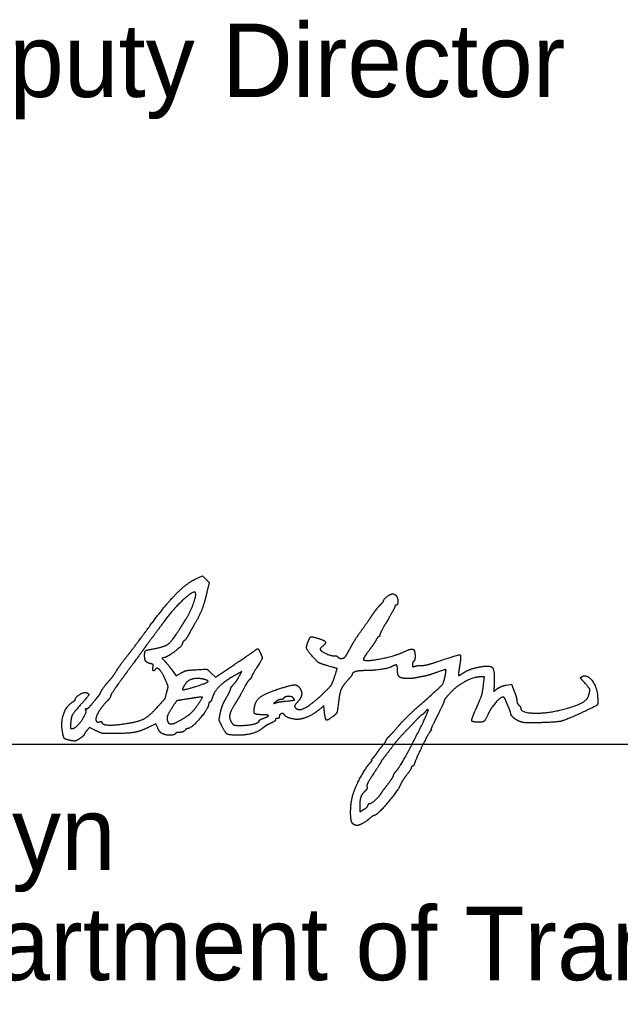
# Model space of a CAD drawing. Extents: x 0 to 34, y -3.9 to 26.2.
# Drawn here: x 25.914 to 27.06, y 4.977 to 6.851 of the extents above; entities that cross this region are included whole.
import ezdxf

# ---------------------------------------------------------------- set-up
doc = ezdxf.new("R2010")
doc.units = 0
doc.layers.add('SH_Data', color=7, linetype='Continuous')
doc.layers.add('SH_Text', color=7, linetype='Continuous')

msp = doc.modelspace()

# ---------------------------------------------------------------- linework, layer by layer
at = {"layer": 'SH_Data'}
msp.add_line((24.7652, 5.4694), (28.2652, 5.4694), dxfattribs=at)
at = {"layer": 'SH_Text'}
for points in [[(26.2505, 5.7846), (26.2631, 5.7904), (26.2694, 5.784), (26.2758, 5.7777), (26.2714, 5.759)], [(26.1905, 5.6346), (26.1855, 5.633), (26.1907, 5.6279)], [(26.2795, 5.6049), (26.2876, 5.5973), (26.3239, 5.6214)], [(26.2043, 5.6112), (26.2129, 5.5997), (26.2217, 5.6049)], [(26.3334, 5.5996), (26.3378, 5.6076), (26.3323, 5.6046)], [(26.7992, 5.5837), (26.8007, 5.5975), (26.7929, 5.5975)], [(26.8431, 5.5821), (26.8527, 5.5836), (26.8578, 5.5701)], [(26.4951, 5.5359), (26.4945, 5.5428), (26.4886, 5.5376)], [(26.1775, 5.5003), (26.1742, 5.5084), (26.1603, 5.5015)], [(26.0589, 5.4953), (26.0474, 5.5011), (26.0423, 5.4953)], [(26.5629, 5.3498), (26.5629, 5.3404), (26.5704, 5.3448)]]:
    msp.add_lwpolyline(points, dxfattribs=at)
for points in [[(26.1609, 5.6927), (26.1906, 5.7333), (26.2324, 5.7762), (26.2505, 5.7846)], [(26.249, 5.7587), (26.2454, 5.7624), (26.2068, 5.7267), (26.1914, 5.7054)], [(26.2307, 5.7067), (26.2401, 5.7216), (26.2521, 5.7556), (26.249, 5.7587)], [(26.2714, 5.759), (26.2664, 5.7378), (26.2572, 5.7142), (26.2478, 5.6983)], [(26.6085, 5.7426), (26.6085, 5.7455), (26.6217, 5.7558), (26.6254, 5.7558)], [(26.6254, 5.7558), (26.6275, 5.7559), (26.6304, 5.7546), (26.632, 5.753)], [(26.632, 5.753), (26.6355, 5.7495), (26.6359, 5.7343), (26.6325, 5.7343)], [(26.5881, 5.7173), (26.5921, 5.7231), (26.5983, 5.7309), (26.6019, 5.7345)], [(26.6019, 5.7345), (26.6055, 5.7382), (26.6085, 5.7418), (26.6085, 5.7426)], [(26.6325, 5.7343), (26.6312, 5.7343), (26.6301, 5.7332), (26.6301, 5.7318)], [(26.5665, 5.6863), (26.5744, 5.6975), (26.5842, 5.7115), (26.5881, 5.7173)], [(26.6301, 5.7318), (26.6301, 5.7304), (26.6236, 5.7183), (26.6157, 5.7049)], [(26.1914, 5.7054), (26.1878, 5.7004), (26.1784, 5.6878), (26.1705, 5.6773)], [(26.2202, 5.69), (26.2234, 5.6952), (26.2282, 5.7027), (26.2307, 5.7067)], [(26.2478, 5.6983), (26.2443, 5.6924), (26.2391, 5.6832), (26.2362, 5.6779)], [(26.6157, 5.7049), (26.6078, 5.6915), (26.6013, 5.6792), (26.6013, 5.6774)], [(26.1207, 5.6392), (26.1296, 5.6506), (26.1477, 5.6746), (26.1609, 5.6927)], [(26.1705, 5.6773), (26.1626, 5.6668), (26.1545, 5.6558), (26.1525, 5.6528)], [(26.1704, 5.6514), (26.191, 5.6551), (26.205, 5.666), (26.2202, 5.69)], [(26.2362, 5.6779), (26.2334, 5.6726), (26.2296, 5.6674), (26.2278, 5.6664)], [(26.5451, 5.6527), (26.5489, 5.66), (26.5585, 5.6751), (26.5665, 5.6863)], [(26.6013, 5.6774), (26.6013, 5.6757), (26.6004, 5.6743), (26.5993, 5.6743)], [(26.2245, 5.661), (26.2245, 5.6572), (26.1987, 5.6372), (26.1905, 5.6346)], [(26.2278, 5.6664), (26.226, 5.6653), (26.2245, 5.6629), (26.2245, 5.661)], [(26.4742, 5.6351), (26.4627, 5.6482), (26.4605, 5.655), (26.4644, 5.6646)], [(26.4644, 5.6646), (26.4682, 5.6736), (26.4713, 5.6746), (26.484, 5.6709)], [(26.484, 5.6709), (26.496, 5.6673), (26.4989, 5.6611), (26.4912, 5.6553)], [(26.594, 5.6677), (26.5922, 5.6641), (26.5861, 5.655), (26.5804, 5.6475)], [(26.5993, 5.6743), (26.5982, 5.6743), (26.5958, 5.6713), (26.594, 5.6677)], [(26.0992, 5.6099), (26.1021, 5.6147), (26.1118, 5.6279), (26.1207, 5.6392)], [(26.1525, 5.6528), (26.1505, 5.6499), (26.1351, 5.6289), (26.1184, 5.6063)], [(26.1525, 5.6393), (26.1525, 5.6461), (26.1566, 5.6489), (26.1704, 5.6514)], [(26.1635, 5.6229), (26.1563, 5.6247), (26.1525, 5.6304), (26.1525, 5.6393)], [(26.3239, 5.6214), (26.3438, 5.6346), (26.3614, 5.6466), (26.363, 5.6479)], [(26.363, 5.6479), (26.3675, 5.6517), (26.3699, 5.6508), (26.3729, 5.6442)], [(26.3729, 5.6442), (26.3773, 5.6346), (26.3763, 5.6305), (26.3661, 5.6146)], [(26.4912, 5.6553), (26.4885, 5.6532), (26.487, 5.6504), (26.4879, 5.649)], [(26.4879, 5.649), (26.4906, 5.6453), (26.5105, 5.6371), (26.5152, 5.6378)], [(26.5358, 5.6365), (26.5371, 5.6382), (26.5413, 5.6454), (26.5451, 5.6527)], [(26.5804, 5.6475), (26.5747, 5.64), (26.5701, 5.6328), (26.5701, 5.6314)], [(26.5701, 5.6314), (26.5701, 5.6262), (26.6297, 5.6371), (26.6477, 5.6457)], [(26.6477, 5.6457), (26.6606, 5.6519), (26.6685, 5.6487), (26.6685, 5.6373)], [(26.7108, 5.6266), (26.7512, 5.6405), (26.7571, 5.6388), (26.753, 5.615)], [(26.1686, 5.6166), (26.1695, 5.6201), (26.1683, 5.6217), (26.1635, 5.6229)], [(26.1907, 5.6279), (26.1935, 5.625), (26.1997, 5.6175), (26.2043, 5.6112)], [(26.4977, 5.62), (26.4869, 5.6231), (26.482, 5.6263), (26.4742, 5.6351)], [(26.5152, 5.6378), (26.5174, 5.6382), (26.52, 5.6374), (26.5208, 5.636)], [(26.5208, 5.636), (26.523, 5.6325), (26.533, 5.6329), (26.5358, 5.6365)], [(26.6661, 5.6275), (26.6648, 5.6267), (26.6637, 5.6239), (26.6637, 5.6212)], [(26.6637, 5.6212), (26.6637, 5.6173), (26.6647, 5.6167), (26.6691, 5.6181)], [(26.6685, 5.6373), (26.6685, 5.6327), (26.6674, 5.6283), (26.6661, 5.6275)], [(26.682, 5.6195), (26.6862, 5.6194), (26.6991, 5.6226), (26.7108, 5.6266)], [(26.0829, 5.588), (26.0895, 5.5953), (26.0937, 5.601), (26.0992, 5.6099)], [(26.1184, 5.6063), (26.1016, 5.5836), (26.0878, 5.5635), (26.0877, 5.5615)], [(26.1728, 5.6118), (26.1704, 5.6079), (26.1672, 5.6115), (26.1686, 5.6166)], [(26.1916, 5.5932), (26.1855, 5.6069), (26.1758, 5.6166), (26.1728, 5.6118)], [(26.2217, 5.6049), (26.2282, 5.6088), (26.2358, 5.6104), (26.2509, 5.6113)], [(26.2509, 5.6113), (26.2712, 5.6125), (26.2714, 5.6125), (26.2795, 5.6049)], [(26.3323, 5.6046), (26.3089, 5.5921), (26.2861, 5.5714), (26.282, 5.5589)], [(26.3661, 5.6146), (26.3608, 5.6064), (26.3565, 5.5988), (26.3565, 5.5977)], [(26.5145, 5.5962), (26.5201, 5.6131), (26.5198, 5.6136), (26.4977, 5.62)], [(26.5485, 5.6023), (26.5485, 5.6014), (26.5443, 5.596), (26.5391, 5.5903)], [(26.5727, 5.6095), (26.5612, 5.6095), (26.5485, 5.6057), (26.5485, 5.6023)], [(26.6235, 5.6169), (26.6179, 5.6139), (26.5877, 5.6095), (26.5727, 5.6095)], [(26.6349, 5.6122), (26.6349, 5.6195), (26.6312, 5.621), (26.6235, 5.6169)], [(26.6542, 5.5945), (26.6418, 5.5946), (26.6349, 5.6009), (26.6349, 5.6122)], [(26.6691, 5.6181), (26.6721, 5.619), (26.6779, 5.6197), (26.682, 5.6195)], [(26.7055, 5.6046), (26.6977, 5.6019), (26.688, 5.5992), (26.6841, 5.5985)], [(26.7261, 5.6), (26.7282, 5.6115), (26.7265, 5.6119), (26.7055, 5.6046)], [(26.753, 5.615), (26.7516, 5.6073), (26.7509, 5.6007), (26.7514, 5.6002)], [(26.7514, 5.6002), (26.7518, 5.5998), (26.7552, 5.6015), (26.7589, 5.6041)], [(26.7589, 5.6041), (26.7662, 5.6092), (26.7844, 5.6155), (26.7981, 5.6176)], [(26.7981, 5.6176), (26.8127, 5.6199), (26.8204, 5.6095), (26.8196, 5.5883)], [(26.0685, 5.5675), (26.0685, 5.5691), (26.0776, 5.5821), (26.0829, 5.588)], [(26.1949, 5.5687), (26.1975, 5.5785), (26.1972, 5.5807), (26.1916, 5.5932)], [(26.2301, 5.5841), (26.2231, 5.5734), (26.2276, 5.5725), (26.2521, 5.58)], [(26.2627, 5.5936), (26.2518, 5.5958), (26.2344, 5.5907), (26.2301, 5.5841)], [(26.2521, 5.58), (26.2713, 5.586), (26.2753, 5.5911), (26.2627, 5.5936)], [(26.3206, 5.5815), (26.326, 5.5875), (26.3285, 5.591), (26.3334, 5.5996)], [(26.346, 5.5835), (26.3379, 5.568), (26.3301, 5.5543), (26.324, 5.5446)], [(26.3529, 5.5927), (26.351, 5.5911), (26.3479, 5.5869), (26.346, 5.5835)], [(26.3565, 5.5977), (26.3565, 5.5966), (26.3549, 5.5944), (26.3529, 5.5927)], [(26.4962, 5.5689), (26.5066, 5.579), (26.5107, 5.5851), (26.5145, 5.5962)], [(26.5391, 5.5903), (26.5306, 5.5808), (26.5249, 5.5682), (26.5233, 5.5555)], [(26.6709, 5.5959), (26.6676, 5.5952), (26.6601, 5.5945), (26.6542, 5.5945)], [(26.6841, 5.5985), (26.6801, 5.5979), (26.6742, 5.5967), (26.6709, 5.5959)], [(26.6813, 5.547), (26.7168, 5.5785), (26.7237, 5.5867), (26.7261, 5.6)], [(26.7929, 5.5975), (26.7802, 5.5975), (26.7464, 5.5791), (26.7342, 5.5655)], [(26.7845, 5.5359), (26.7936, 5.5558), (26.7976, 5.5689), (26.7992, 5.5837)], [(26.8196, 5.5883), (26.8189, 5.5699), (26.8188, 5.5701), (26.8265, 5.5757)], [(26.9897, 5.5889), (26.9844, 5.5946), (26.9841, 5.5972), (26.9888, 5.599)], [(26.9888, 5.599), (26.9974, 5.6023), (27.0158, 5.5773), (27.0168, 5.5611)], [(26.9988, 5.5598), (27.0028, 5.5716), (27.0012, 5.5765), (26.9897, 5.5889)], [(26.0205, 5.5555), (26.0206, 5.5592), (26.0373, 5.5692), (26.0411, 5.5677)], [(26.0411, 5.5677), (26.0471, 5.5655), (26.0448, 5.5606), (26.0305, 5.5447)], [(26.0661, 5.5632), (26.0674, 5.5648), (26.0685, 5.5667), (26.0685, 5.5675)], [(26.1753, 5.5382), (26.1914, 5.5558), (26.1917, 5.5563), (26.1949, 5.5687)], [(26.3081, 5.5574), (26.3125, 5.565), (26.3163, 5.5727), (26.3166, 5.5745)], [(26.3166, 5.5745), (26.3169, 5.5762), (26.3186, 5.5794), (26.3206, 5.5815)], [(26.3623, 5.5407), (26.3644, 5.552), (26.3806, 5.5653), (26.3999, 5.5718)], [(26.3999, 5.5718), (26.4317, 5.5824), (26.4451, 5.5828), (26.4502, 5.5733)], [(26.4392, 5.5401), (26.4445, 5.5314), (26.4712, 5.5449), (26.4962, 5.5689)], [(26.4502, 5.5733), (26.4534, 5.5673), (26.45, 5.5559), (26.4426, 5.548)], [(26.7342, 5.5655), (26.7284, 5.5591), (26.7237, 5.5525), (26.7237, 5.5509)], [(26.8265, 5.5757), (26.8303, 5.5783), (26.8377, 5.5812), (26.8431, 5.5821)], [(26.8578, 5.5701), (26.8606, 5.5626), (26.8629, 5.5545), (26.8629, 5.552)], [(25.9956, 5.4939), (25.9927, 5.5124), (26.0034, 5.5424), (26.0158, 5.5501)], [(26.0158, 5.5501), (26.0184, 5.5517), (26.0205, 5.5541), (26.0205, 5.5555)], [(26.0417, 5.537), (26.0431, 5.5366), (26.0486, 5.5417), (26.054, 5.5483)], [(26.054, 5.5483), (26.0593, 5.5549), (26.0648, 5.5616), (26.0661, 5.5632)], [(26.0803, 5.5508), (26.0705, 5.5411), (26.0581, 5.519), (26.0599, 5.5143)], [(26.0877, 5.5615), (26.0876, 5.5595), (26.0843, 5.5547), (26.0803, 5.5508)], [(26.2329, 5.5553), (26.2151, 5.5527), (26.2131, 5.5515), (26.2058, 5.5403)], [(26.2254, 5.5176), (26.2366, 5.5245), (26.2476, 5.5351), (26.2553, 5.5463)], [(26.2503, 5.5579), (26.2447, 5.557), (26.2368, 5.5558), (26.2329, 5.5553)], [(26.2748, 5.5465), (26.2747, 5.538), (26.2416, 5.4991), (26.2345, 5.4991)], [(26.2553, 5.5463), (26.2631, 5.5576), (26.2622, 5.5598), (26.2503, 5.5579)], [(26.2769, 5.5495), (26.2758, 5.5495), (26.2749, 5.5482), (26.2748, 5.5465)], [(26.282, 5.5589), (26.2803, 5.5537), (26.278, 5.5495), (26.2769, 5.5495)], [(26.2972, 5.5295), (26.2988, 5.5372), (26.3037, 5.5498), (26.3081, 5.5574)], [(26.4031, 5.5505), (26.3986, 5.5468), (26.3986, 5.5467), (26.4033, 5.5484)], [(26.412, 5.5543), (26.4097, 5.5543), (26.4057, 5.5526), (26.4031, 5.5505)], [(26.4033, 5.5484), (26.4059, 5.5493), (26.4135, 5.5506), (26.4201, 5.5512)], [(26.4175, 5.5564), (26.4168, 5.5553), (26.4143, 5.5543), (26.412, 5.5543)], [(26.436, 5.5575), (26.4332, 5.5609), (26.4198, 5.5601), (26.4175, 5.5564)], [(26.4201, 5.5512), (26.4368, 5.5527), (26.4392, 5.5537), (26.436, 5.5575)], [(26.4426, 5.548), (26.4398, 5.5451), (26.4383, 5.5415), (26.4392, 5.5401)], [(26.5233, 5.5555), (26.5205, 5.533), (26.5187, 5.5275), (26.5131, 5.5231)], [(26.6372, 5.5042), (26.6444, 5.5126), (26.6642, 5.5319), (26.6813, 5.547)], [(26.7237, 5.5509), (26.7237, 5.5494), (26.7177, 5.5365), (26.7105, 5.5224)], [(26.8361, 5.5591), (26.8318, 5.5591), (26.8135, 5.5386), (26.8088, 5.5284)], [(26.8417, 5.5525), (26.8402, 5.5561), (26.8377, 5.5591), (26.8361, 5.5591)], [(26.8476, 5.5383), (26.8458, 5.5425), (26.8432, 5.5489), (26.8417, 5.5525)], [(26.8629, 5.552), (26.8629, 5.5495), (26.8645, 5.5458), (26.8665, 5.5438)], [(26.9499, 5.5355), (26.9736, 5.5417), (26.9966, 5.5531), (26.9988, 5.5598)], [(27.0168, 5.5611), (27.0177, 5.5458), (27.0151, 5.5426), (26.9917, 5.5317)], [(26.0305, 5.5447), (26.0168, 5.5295), (26.0118, 5.5194), (26.0112, 5.5055)], [(26.016, 5.4995), (26.0224, 5.5005), (26.0425, 5.5289), (26.0405, 5.5341)], [(26.0405, 5.5341), (26.0397, 5.5361), (26.0403, 5.5374), (26.0417, 5.537)], [(26.1188, 5.5089), (26.1415, 5.5125), (26.1611, 5.5227), (26.1753, 5.5382)], [(26.2058, 5.5403), (26.1976, 5.5277), (26.1944, 5.5179), (26.1967, 5.512)], [(26.2992, 5.5055), (26.2948, 5.5146), (26.2946, 5.5169), (26.2972, 5.5295)], [(26.324, 5.5446), (26.316, 5.5319), (26.3138, 5.5167), (26.3189, 5.5099)], [(26.3758, 5.5255), (26.3643, 5.5255), (26.3603, 5.5301), (26.3623, 5.5407)], [(26.4188, 5.5257), (26.4168, 5.5289), (26.4093, 5.5258), (26.4093, 5.5216)], [(26.4886, 5.5376), (26.4792, 5.5295), (26.4592, 5.5188), (26.4501, 5.5172)], [(26.5131, 5.5231), (26.5014, 5.5138), (26.497, 5.517), (26.4951, 5.5359)], [(26.6346, 5.4204), (26.6422, 5.4291), (26.6955, 5.5329), (26.6934, 5.535)], [(26.6877, 5.5309), (26.6853, 5.5279), (26.6827, 5.5255), (26.6819, 5.5255)], [(26.6934, 5.535), (26.6927, 5.5357), (26.6901, 5.5339), (26.6877, 5.5309)], [(26.7919, 5.5111), (26.7774, 5.5111), (26.7758, 5.5165), (26.7845, 5.5359)], [(26.8088, 5.5284), (26.8031, 5.516), (26.7983, 5.5111), (26.7919, 5.5111)], [(26.851, 5.5287), (26.8509, 5.5299), (26.8494, 5.5342), (26.8476, 5.5383)], [(26.8666, 5.5132), (26.8596, 5.5165), (26.8511, 5.5249), (26.851, 5.5287)], [(26.8665, 5.5438), (26.8685, 5.5419), (26.8701, 5.5392), (26.8701, 5.5379)], [(26.8701, 5.5379), (26.8701, 5.5293), (26.9207, 5.5278), (26.9499, 5.5355)], [(26.9917, 5.5317), (26.9569, 5.5153), (26.9359, 5.5106), (26.8965, 5.5101)], [(26.0599, 5.5143), (26.0608, 5.512), (26.0631, 5.511), (26.0661, 5.5118)], [(26.0661, 5.5118), (26.0687, 5.5125), (26.0709, 5.5122), (26.0709, 5.511)], [(26.0709, 5.511), (26.0709, 5.5064), (26.0965, 5.5052), (26.1188, 5.5089)], [(26.1967, 5.512), (26.1987, 5.5068), (26.2122, 5.5094), (26.2254, 5.5176)], [(26.3189, 5.5099), (26.3217, 5.5061), (26.3253, 5.5051), (26.3365, 5.5051)], [(26.3365, 5.5051), (26.3505, 5.5051), (26.3709, 5.5102), (26.3709, 5.5137)], [(26.3709, 5.5137), (26.3709, 5.5148), (26.3746, 5.5169), (26.3792, 5.5186)], [(26.3792, 5.5186), (26.3895, 5.5223), (26.3879, 5.5255), (26.3758, 5.5255)], [(26.3967, 5.5109), (26.3893, 5.5076), (26.3817, 5.5031), (26.3775, 5.4996)], [(26.4021, 5.5158), (26.4021, 5.5145), (26.3997, 5.5123), (26.3967, 5.5109)], [(26.4057, 5.5183), (26.4037, 5.5183), (26.4021, 5.5172), (26.4021, 5.5158)], [(26.4093, 5.5216), (26.4093, 5.5198), (26.4077, 5.5183), (26.4057, 5.5183)], [(26.4501, 5.5172), (26.4415, 5.5156), (26.4217, 5.521), (26.4188, 5.5257)], [(26.6731, 5.5177), (26.669, 5.5134), (26.6585, 5.5023), (26.6497, 5.4931)], [(26.6819, 5.5255), (26.6812, 5.5255), (26.6772, 5.522), (26.6731, 5.5177)], [(26.7105, 5.5224), (26.7032, 5.5083), (26.6981, 5.4967), (26.6991, 5.4967)], [(26.8965, 5.5101), (26.8816, 5.5099), (26.8713, 5.511), (26.8666, 5.5132)], [(26.0122, 5.4761), (26.0013, 5.4782), (25.9975, 5.4823), (25.9956, 5.4939)], [(26.0112, 5.5055), (26.011, 5.4999), (26.0118, 5.4989), (26.016, 5.4995)], [(26.0423, 5.4953), (26.0396, 5.4921), (26.0373, 5.4887), (26.0373, 5.4877)], [(26.0897, 5.4895), (26.0741, 5.4895), (26.0682, 5.4906), (26.0589, 5.4953)], [(26.1603, 5.5015), (26.1448, 5.4938), (26.1196, 5.4895), (26.0897, 5.4895)], [(26.1857, 5.4897), (26.1831, 5.4911), (26.1794, 5.4959), (26.1775, 5.5003)], [(26.2113, 5.4895), (26.2093, 5.4863), (26.1918, 5.4864), (26.1857, 5.4897)], [(26.2195, 5.4919), (26.2158, 5.4919), (26.2121, 5.4908), (26.2113, 5.4895)], [(26.2293, 5.4955), (26.2276, 5.4935), (26.2233, 5.4919), (26.2195, 5.4919)], [(26.2345, 5.4991), (26.2333, 5.4991), (26.2309, 5.4975), (26.2293, 5.4955)], [(26.331, 5.4864), (26.3135, 5.4865), (26.3065, 5.4907), (26.2992, 5.5055)], [(26.3775, 5.4996), (26.3698, 5.4932), (26.3455, 5.4863), (26.331, 5.4864)], [(26.6187, 5.4838), (26.6217, 5.4867), (26.63, 5.4958), (26.6372, 5.5042)], [(26.6497, 5.4931), (26.6409, 5.4838), (26.631, 5.4726), (26.6277, 5.4681)], [(26.6983, 5.4949), (26.6956, 5.493), (26.6704, 5.442), (26.6674, 5.4325)], [(26.6991, 5.4967), (26.7001, 5.4966), (26.6997, 5.4958), (26.6983, 5.4949)], [(26.0289, 5.4802), (26.0224, 5.4758), (26.0188, 5.4749), (26.0122, 5.4761)], [(26.0373, 5.4877), (26.0373, 5.4867), (26.0335, 5.4833), (26.0289, 5.4802)], [(26.6067, 5.4668), (26.6103, 5.4711), (26.6133, 5.4755), (26.6133, 5.4766)], [(26.6133, 5.4766), (26.6134, 5.4778), (26.6158, 5.481), (26.6187, 5.4838)], [(26.5887, 5.4435), (26.591, 5.4459), (26.5945, 5.4504), (26.5965, 5.4535)], [(26.5965, 5.4535), (26.5985, 5.4566), (26.6031, 5.4625), (26.6067, 5.4668)], [(26.6277, 5.4681), (26.6196, 5.4572), (26.6091, 5.4434), (26.6061, 5.4398)], [(26.5527, 5.3811), (26.5586, 5.3959), (26.5757, 5.4258), (26.5828, 5.4337)], [(26.5828, 5.4337), (26.5855, 5.4367), (26.587, 5.4391), (26.5861, 5.4391)], [(26.5861, 5.4391), (26.5852, 5.4391), (26.5864, 5.4411), (26.5887, 5.4435)], [(26.6037, 5.4359), (26.6037, 5.4354), (26.5974, 5.4254), (26.5896, 5.4138)], [(26.6061, 5.4398), (26.6048, 5.4382), (26.6037, 5.4365), (26.6037, 5.4359)], [(26.6277, 5.4101), (26.6277, 5.4114), (26.6308, 5.4161), (26.6346, 5.4204)], [(26.6613, 5.4246), (26.6613, 5.4232), (26.657, 5.4165), (26.6518, 5.4095)], [(26.6635, 5.4271), (26.6623, 5.4271), (26.6613, 5.426), (26.6613, 5.4246)], [(26.6674, 5.4325), (26.6665, 5.4295), (26.6648, 5.4271), (26.6635, 5.4271)], [(26.5896, 5.4138), (26.5809, 5.4008), (26.576, 5.391), (26.5767, 5.3883)], [(26.6175, 5.3943), (26.6231, 5.4017), (26.6277, 5.4088), (26.6277, 5.4101)], [(26.6518, 5.4095), (26.6466, 5.4026), (26.6415, 5.3947), (26.6404, 5.3918)], [(26.5509, 5.3167), (26.545, 5.3204), (26.5462, 5.3647), (26.5527, 5.3811)], [(26.573, 5.3797), (26.5671, 5.3745), (26.5629, 5.3622), (26.5629, 5.3498)], [(26.5767, 5.3883), (26.5774, 5.3858), (26.5758, 5.3821), (26.573, 5.3797)], [(26.5821, 5.3563), (26.584, 5.3551), (26.6007, 5.3703), (26.6049, 5.377)], [(26.6404, 5.3918), (26.6368, 5.382), (26.5956, 5.3335), (26.5909, 5.3335)], [(26.6049, 5.377), (26.6062, 5.3792), (26.6119, 5.3869), (26.6175, 5.3943)], [(26.5704, 5.3448), (26.5746, 5.3472), (26.5785, 5.351), (26.5791, 5.3533)], [(26.5791, 5.3533), (26.5797, 5.3556), (26.5811, 5.3569), (26.5821, 5.3563)], [(26.5834, 5.3289), (26.5772, 5.3232), (26.5613, 5.3143), (26.5574, 5.3143)], [(26.5909, 5.3335), (26.5895, 5.3335), (26.5862, 5.3314), (26.5834, 5.3289)], [(26.5574, 5.3143), (26.5558, 5.3144), (26.5529, 5.3154), (26.5509, 5.3167)]]:
    msp.add_open_spline(points, degree=2, dxfattribs=at)

# ---------------------------------------------------------------- texts
for s, p in [('District       Deputy Director', (24.7189, 6.7031)), ('Pamela Boratyn', (24.7652, 5.2294)), ('Director, Department of Transportation', (24.7652, 5.0194))]:
    msp.add_text(s, height=0.14, dxfattribs=at).set_placement(p)

doc.saveas('drawing.dxf')
